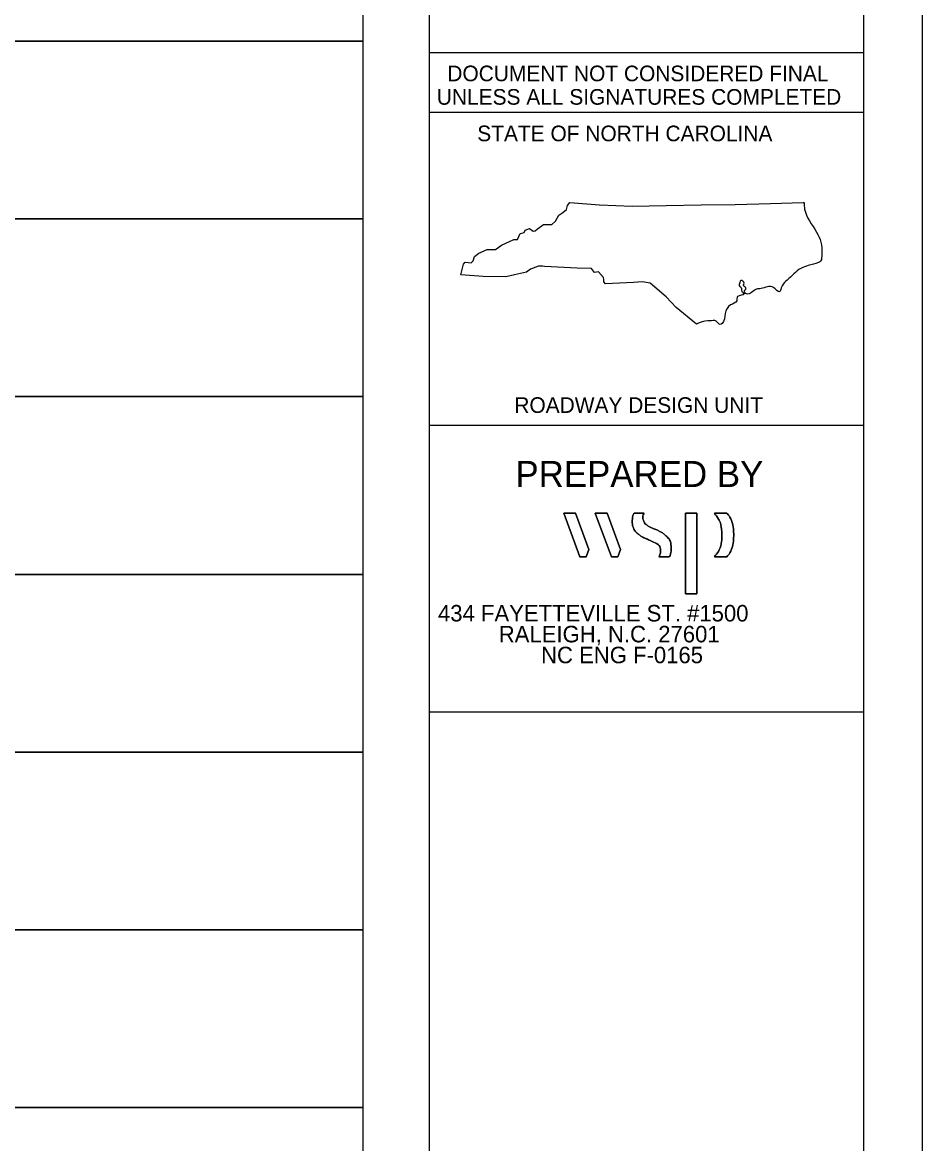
# Model space of a CAD drawing. Extents: x 1553884 to 1554215, y 810431 to 810779.
# Drawn here: x 1554125.27 to 1554156.35, y 810698.51 to 810737.21 of the extents above; entities that cross this region are included whole.
import ezdxf

# ---------------------------------------------------------------- set-up
doc = ezdxf.new("R2010")
doc.units = 0
for name, color, linetype in [('Old_Level_1', 7, 'Continuous'), ('Old_Level_11', 7, 'Continuous'), ('Old_Level_2', 7, 'Continuous'), ('Prop Dimension', 7, 'Continuous'), ('Prop Lane Arrow CELL', 7, 'Continuous'), ('Typical Arrow Superelevation CELL', 7, 'Continuous')]:
    doc.layers.add(name, color=color, linetype=linetype)

msp = doc.modelspace()

# ---------------------------------------------------------------- linework, layer by layer
at = {"layer": 'Old_Level_1'}
msp.add_line((1554152.261, 810730.981), (1554152.26, 810730.988), dxfattribs=at)
for points in [[(1554140.411, 810728.49), (1554140.505, 810728.861), (1554140.563, 810728.928), (1554140.763, 810728.914), (1554140.831, 810728.98), (1554140.884, 810729.125), (1554141.034, 810729.242), (1554141.313, 810729.369), (1554141.607, 810729.372), (1554141.815, 810729.518), (1554142.093, 810729.641), (1554142.232, 810729.716), (1554142.367, 810729.72), (1554142.457, 810729.923), (1554142.59, 810729.961), (1554142.634, 810730.033), (1554142.776, 810730.1), (1554142.905, 810730.004), (1554142.975, 810730.011), (1554143.055, 810730.084), (1554143.264, 810730.235), (1554143.55, 810730.238), (1554143.678, 810730.348), (1554143.789, 810730.552), (1554143.929, 810730.65), (1554144.058, 810730.75), (1554144.086, 810730.886), (1554144.17, 810730.988)], [(1554144.17, 810730.988), (1554145.195, 810730.915), (1554146.328, 810730.871), (1554147.502, 810730.885), (1554148.701, 810730.907), (1554149.88, 810730.926), (1554151.099, 810730.963), (1554152.227, 810730.988), (1554152.26, 810730.988)], [(1554148.542, 810726.794), (1554147.846, 810727.366), (1554147.492, 810727.733), (1554146.948, 810728.203), (1554146.667, 810728.248), (1554146.371, 810728.234), (1554145.397, 810728.186), (1554145.341, 810728.257), (1554145.34, 810728.329), (1554145.336, 810728.401), (1554145.157, 810728.598), (1554145.019, 810728.58), (1554144.923, 810728.714), (1554144.424, 810728.728), (1554143.295, 810728.779), (1554143.224, 810728.792), (1554143.089, 810728.792), (1554142.81, 810728.693), (1554142.675, 810728.587), (1554142.261, 810728.499), (1554141.967, 810728.432), (1554141.18, 810728.442), (1554140.411, 810728.49)]]:
    msp.add_lwpolyline(points, dxfattribs=at)
for points in [[(1554152.261, 810730.981), (1554152.277, 810730.761), (1554152.692, 810729.972), (1554152.842, 810729.622), (1554152.874, 810729.261), (1554152.856, 810729.029)], [(1554152.405, 810728.82), (1554152.149, 810728.718), (1554151.678, 810728.313), (1554151.497, 810728.112), (1554151.406, 810727.907), (1554151.204, 810728.061), (1554150.774, 810728.021), (1554150.618, 810728), (1554150.275, 810727.838), (1554150.209, 810727.887), (1554150.206, 810727.953), (1554150.264, 810728.019), (1554150.164, 810728.141), (1554150.189, 810728.206), (1554150.074, 810728.301), (1554150.036, 810728.234), (1554150.037, 810728.095), (1554150.102, 810728.031), (1554150.099, 810727.963), (1554150.185, 810727.827), (1554149.959, 810727.742), (1554149.933, 810727.596), (1554149.724, 810727.455), (1554149.538, 810727.16), (1554149.427, 810726.817), (1554149.36, 810726.783), (1554149.227, 810726.891), (1554149, 810726.908), (1554148.934, 810726.909), (1554148.542, 810726.794)], [(1554152.856, 810729.029), (1554152.822, 810728.955), (1554152.757, 810728.917), (1554152.405, 810728.82)]]:
    msp.add_spline(points, degree=3, dxfattribs=at)
at = {"layer": 'Old_Level_2'}
for p, q in [((1554139.321, 810617.805), (1554139.325, 810776.052)), ((1554154.321, 810617.805), (1554154.325, 810776.052)), ((1554154.325, 810736.164), (1554139.325, 810736.164)), ((1554154.325, 810734.094), (1554139.325, 810734.094)), ((1554154.325, 810723.294), (1554139.325, 810723.294)), ((1554154.325, 810713.394), (1554139.325, 810713.394))]:
    msp.add_line(p, q, dxfattribs=at)
at = {"layer": 'Prop Dimension'}
for points in [[(1554083.164, 810736.565), (1554077.027, 810736.565), (1554077.027, 810742.702), (1554137.027, 810742.702), (1554137.027, 810736.565), (1554083.164, 810736.565), (1554083.164, 810742.702)], [(1554083.164, 810730.428), (1554077.027, 810730.428), (1554077.027, 810736.565), (1554137.027, 810736.565), (1554137.027, 810730.428), (1554083.164, 810730.428), (1554083.164, 810736.565)], [(1554083.164, 810724.292), (1554077.027, 810724.292), (1554077.027, 810730.428), (1554137.027, 810730.428), (1554137.027, 810724.292), (1554083.164, 810724.292), (1554083.164, 810730.428)], [(1554083.164, 810718.155), (1554077.027, 810718.155), (1554077.027, 810724.292), (1554137.027, 810724.292), (1554137.027, 810718.155), (1554083.164, 810718.155), (1554083.164, 810724.292)], [(1554083.164, 810712.019), (1554077.027, 810712.019), (1554077.027, 810718.155), (1554137.027, 810718.155), (1554137.027, 810712.019), (1554083.164, 810712.019), (1554083.164, 810718.155)], [(1554083.164, 810705.882), (1554077.027, 810705.882), (1554077.027, 810712.019), (1554137.027, 810712.019), (1554137.027, 810705.882), (1554083.164, 810705.882), (1554083.164, 810712.019)], [(1554083.164, 810699.745), (1554077.027, 810699.745), (1554077.027, 810705.882), (1554137.027, 810705.882), (1554137.027, 810699.745), (1554083.164, 810699.745), (1554083.164, 810705.882)], [(1554083.164, 810693.609), (1554077.027, 810693.609), (1554077.027, 810699.745), (1554137.027, 810699.745), (1554137.027, 810693.609), (1554083.164, 810693.609), (1554083.164, 810699.745)]]:
    msp.add_lwpolyline(points, dxfattribs=at)
at = {"layer": 'Prop Lane Arrow CELL'}
msp.add_line((1554156.35, 810614.43), (1554156.35, 810779.427), dxfattribs=at)
at = {"layer": 'Typical Arrow Superelevation CELL'}
for p, q in [((1554144.52, 810718.76), (1554143.963, 810720.269)), ((1554143.963, 810720.269), (1554144.369, 810720.269)), ((1554144.369, 810720.269), (1554144.83, 810719.018)), ((1554145.607, 810718.76), (1554145.051, 810720.269)), ((1554145.051, 810720.269), (1554145.456, 810720.269)), ((1554145.456, 810720.269), (1554145.918, 810719.018)), ((1554148.166, 810717.48), (1554148.166, 810720.269)), ((1554148.166, 810720.269), (1554148.554, 810720.269)), ((1554148.554, 810720.269), (1554148.554, 810717.48)), ((1554144.735, 810718.76), (1554144.52, 810718.76)), ((1554144.83, 810719.018), (1554144.735, 810718.76)), ((1554145.823, 810718.76), (1554145.607, 810718.76)), ((1554145.918, 810719.018), (1554145.823, 810718.76)), ((1554148.554, 810717.48), (1554148.166, 810717.48))]:
    msp.add_line(p, q, dxfattribs=at)
for points in [[(1554144.369, 810720.269), (1554143.963, 810720.269), (1554144.52, 810718.76), (1554144.735, 810718.76), (1554144.83, 810719.018), (1554144.369, 810720.269)], [(1554145.456, 810720.269), (1554145.051, 810720.269), (1554145.607, 810718.76), (1554145.823, 810718.76), (1554145.918, 810719.018), (1554145.456, 810720.269)], [(1554148.554, 810717.48), (1554148.554, 810720.269), (1554148.166, 810720.269), (1554148.166, 810717.48), (1554148.554, 810717.48)]]:
    msp.add_lwpolyline(points, dxfattribs=at)
for points in [[(1554146.33, 810720.045), (1554146.336, 810720.123), (1554146.35, 810720.199), (1554146.382, 810720.269), (1554146.382, 810720.269), (1554146.737, 810720.269), (1554146.737, 810720.269), (1554146.707, 810720.216), (1554146.679, 810720.118), (1554146.711, 810720.021), (1554146.74, 810719.933), (1554146.8, 810719.874), (1554146.877, 810719.824), (1554146.967, 810719.766), (1554147.073, 810719.733), (1554147.17, 810719.688), (1554147.272, 810719.641), (1554147.371, 810719.591), (1554147.456, 810719.517), (1554147.58, 810719.41), (1554147.655, 810719.282), (1554147.667, 810719.118), (1554147.669, 810719.098), (1554147.67, 810719.078), (1554147.67, 810719.059), (1554147.67, 810718.955), (1554147.653, 810718.853), (1554147.607, 810718.76), (1554147.607, 810718.76), (1554147.243, 810718.76), (1554147.243, 810718.76), (1554147.279, 810718.821), (1554147.307, 810718.904), (1554147.302, 810718.981), (1554147.289, 810719.171), (1554147.057, 810719.275), (1554146.862, 810719.362), (1554146.833, 810719.375), (1554146.804, 810719.388), (1554146.776, 810719.401), (1554146.69, 810719.441), (1554146.606, 810719.487), (1554146.534, 810719.547), (1554146.458, 810719.61), (1554146.401, 810719.672), (1554146.366, 810719.764), (1554146.335, 810719.845), (1554146.324, 810719.932), (1554146.328, 810720.018), (1554146.328, 810720.027), (1554146.329, 810720.036), (1554146.33, 810720.045)], [(1554146.33, 810720.045), (1554146.329, 810720.036), (1554146.328, 810720.027), (1554146.328, 810720.018), (1554146.324, 810719.932), (1554146.335, 810719.845), (1554146.366, 810719.764), (1554146.401, 810719.672), (1554146.458, 810719.61), (1554146.534, 810719.547), (1554146.606, 810719.487), (1554146.69, 810719.441), (1554146.776, 810719.401), (1554146.804, 810719.388), (1554146.833, 810719.375), (1554146.862, 810719.362), (1554147.057, 810719.275), (1554147.289, 810719.171), (1554147.302, 810718.981), (1554147.307, 810718.904), (1554147.279, 810718.821), (1554147.243, 810718.76), (1554147.243, 810718.76), (1554147.607, 810718.76), (1554147.607, 810718.76), (1554147.653, 810718.853), (1554147.67, 810718.955), (1554147.67, 810719.059), (1554147.67, 810719.078), (1554147.669, 810719.098), (1554147.667, 810719.118), (1554147.655, 810719.282), (1554147.58, 810719.41), (1554147.456, 810719.517), (1554147.371, 810719.591), (1554147.272, 810719.641), (1554147.17, 810719.688), (1554147.073, 810719.733), (1554146.967, 810719.766), (1554146.877, 810719.824), (1554146.8, 810719.874), (1554146.74, 810719.933), (1554146.711, 810720.021), (1554146.679, 810720.118), (1554146.707, 810720.216), (1554146.737, 810720.269), (1554146.737, 810720.269), (1554146.382, 810720.269), (1554146.382, 810720.269), (1554146.35, 810720.199), (1554146.336, 810720.123), (1554146.33, 810720.045)], [(1554149.421, 810719.516), (1554149.421, 810719.832), (1554149.306, 810720.096), (1554149.154, 810720.269), (1554149.154, 810720.269), (1554149.594, 810720.269), (1554149.594, 810720.269), (1554149.738, 810720.093), (1554149.828, 810719.794), (1554149.828, 810719.516), (1554149.828, 810719.516), (1554149.828, 810719.515), (1554149.828, 810719.515), (1554149.828, 810719.236), (1554149.738, 810718.936), (1554149.593, 810718.76), (1554149.593, 810718.76), (1554149.153, 810718.76), (1554149.153, 810718.76), (1554149.305, 810718.933), (1554149.421, 810719.198), (1554149.421, 810719.515), (1554149.421, 810719.515), (1554149.421, 810719.516), (1554149.421, 810719.516)], [(1554149.421, 810719.516), (1554149.421, 810719.516), (1554149.421, 810719.515), (1554149.421, 810719.515), (1554149.421, 810719.198), (1554149.305, 810718.933), (1554149.153, 810718.76), (1554149.153, 810718.76), (1554149.593, 810718.76), (1554149.593, 810718.76), (1554149.738, 810718.936), (1554149.828, 810719.236), (1554149.828, 810719.515), (1554149.828, 810719.515), (1554149.828, 810719.516), (1554149.828, 810719.516), (1554149.828, 810719.794), (1554149.738, 810720.093), (1554149.594, 810720.269), (1554149.594, 810720.269), (1554149.154, 810720.269), (1554149.154, 810720.269), (1554149.306, 810720.096), (1554149.421, 810719.832), (1554149.421, 810719.516)]]:
    msp.add_open_spline(points, degree=3, dxfattribs=at)

# ---------------------------------------------------------------- texts
at = {"layer": 'Old_Level_11'}
for s, p in [('434 FAYETTEVILLE ST. #1500', (1554139.619, 810716.529)), ('RALEIGH, N.C. 27601', (1554141.717, 810715.808)), ('NC ENG F-0165', (1554143.177, 810715.087))]:
    msp.add_text(s, height=0.57009, rotation=360, dxfattribs=at).set_placement(p)
at = {"layer": 'Typical Arrow Superelevation CELL'}
for s, height, p in [('DOCUMENT NOT CONSIDERED FINAL', 0.54, (1554139.942, 810735.178)), ('UNLESS ALL SIGNATURES COMPLETED', 0.54, (1554139.578, 810734.368)), ('STATE OF NORTH CAROLINA', 0.54, (1554140.975, 810733.107)), ('ROADWAY DESIGN UNIT', 0.54, (1554142.255, 810723.729)), ('PREPARED BY', 0.9, (1554142.292, 810721.17))]:
    msp.add_text(s, height=height, dxfattribs=at).set_placement(p)

doc.saveas('drawing.dxf')
